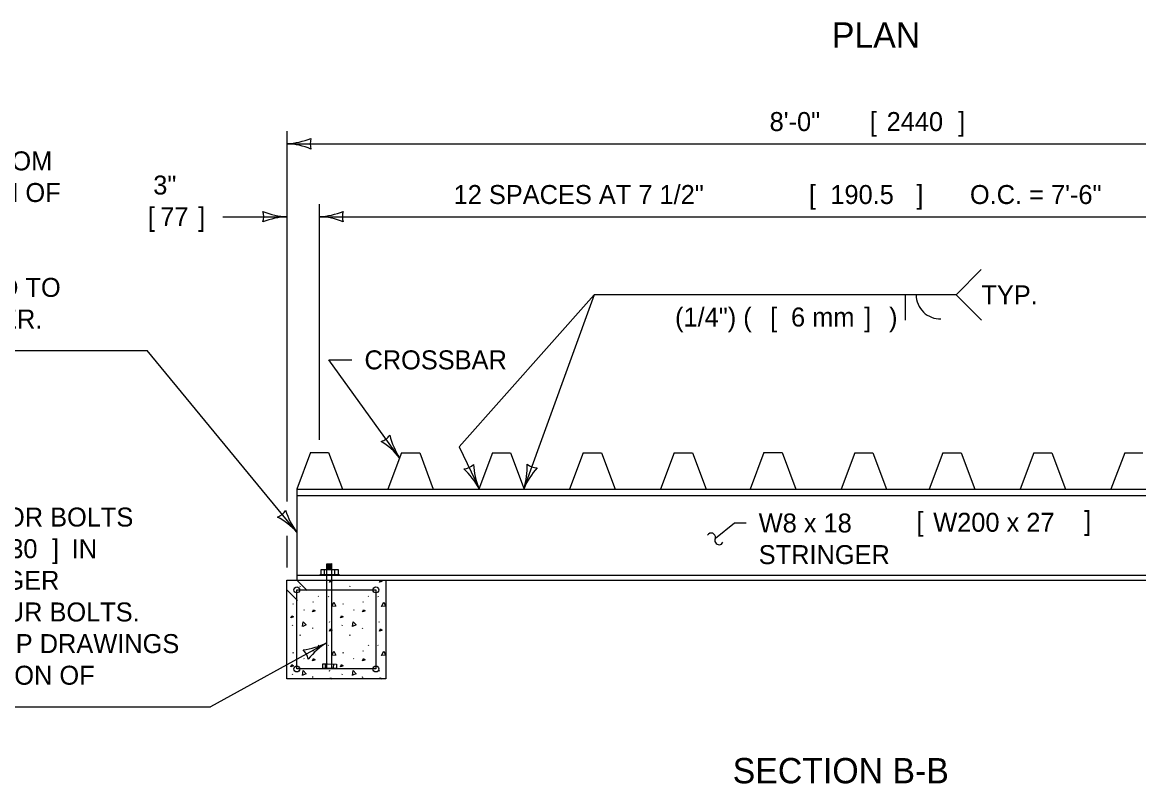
# Model space of a CAD drawing. Extents: x 49991.4 to 50021, y 49987.6 to 50011.4.
# Drawn here: x 50010.101 to 50013.631, y 49993.516 to 49995.923 of the extents above; entities that cross this region are included whole.
import ezdxf

# ---------------------------------------------------------------- set-up
doc = ezdxf.new("R2010")
doc.units = 0
for name, color, linetype in [('Level 1', 7, 'Continuous'), ('Level 2', 7, 'Continuous'), ('Level 3', 7, 'Continuous')]:
    doc.layers.add(name, color=color, linetype=linetype)

msp = doc.modelspace()

# ---------------------------------------------------------------- linework, layer by layer
at = {"layer": 'Level 1'}
for p, q in [((50011.0124, 49994.5626), (50010.9693, 49994.4468)), ((50011.0124, 49994.5626), (50011.0699, 49994.5626)), ((50011.0699, 49994.5626), (50011.1133, 49994.4468)), ((50011.3002, 49994.5619), (50011.2571, 49994.4468)), ((50011.3002, 49994.5619), (50011.3577, 49994.5619)), ((50011.3577, 49994.5619), (50011.4008, 49994.4468)), ((50011.5877, 49994.5619), (50011.5445, 49994.4468)), ((50011.5877, 49994.5619), (50011.6451, 49994.5619)), ((50011.6451, 49994.5619), (50011.6883, 49994.4468)), ((50011.8751, 49994.5619), (50011.8319, 49994.4468)), ((50011.8751, 49994.5619), (50011.9327, 49994.5617)), ((50011.9327, 49994.5617), (50011.9758, 49994.4468)), ((50012.1626, 49994.5617), (50012.1194, 49994.4468)), ((50012.1626, 49994.5617), (50012.2202, 49994.5617)), ((50012.2202, 49994.5617), (50012.2633, 49994.4468)), ((50012.4464, 49994.5623), (50012.4029, 49994.4468)), ((50012.4464, 49994.5623), (50012.504, 49994.5623)), ((50012.504, 49994.5623), (50012.5471, 49994.4468)), ((50012.7334, 49994.5622), (50012.6901, 49994.4468)), ((50012.7334, 49994.5622), (50012.7909, 49994.5622)), ((50012.7909, 49994.5622), (50012.8339, 49994.4468)), ((50013.012, 49994.5622), (50012.9686, 49994.4468)), ((50013.012, 49994.5622), (50013.0695, 49994.5622)), ((50013.0695, 49994.5622), (50013.1127, 49994.4468)), ((50013.2995, 49994.5622), (50013.2561, 49994.4468)), ((50013.2995, 49994.5622), (50013.3571, 49994.5622)), ((50013.3571, 49994.5622), (50013.4002, 49994.4468)), ((50013.5871, 49994.5622), (50013.5436, 49994.4468)), ((50013.5871, 49994.5622), (50013.6444, 49994.5622)), ((50010.9693, 49994.4468), (50014.5501, 49994.4468)), ((50010.9693, 49994.4468), (50010.9693, 49994.1596)), ((50010.9693, 49994.4271), (50014.5501, 49994.4271)), ((50011.064, 49994.2103), (50011.0797, 49994.2114)), ((50011.064, 49993.8801), (50011.064, 49994.2103)), ((50011.0797, 49993.8798), (50011.0797, 49994.2114)), ((50010.9693, 49994.1748), (50014.5501, 49994.1748)), ((50011.1041, 49994.1756), (50011.0416, 49994.1756)), ((50011.0416, 49994.1756), (50011.0416, 49994.1748)), ((50011.046, 49994.1756), (50011.046, 49994.1926)), ((50011.046, 49994.1926), (50011.064, 49994.1926)), ((50011.0572, 49994.1756), (50011.0572, 49994.1926)), ((50011.064, 49994.2075), (50011.0797, 49994.2083)), ((50011.064, 49994.2044), (50011.0797, 49994.2052)), ((50011.064, 49994.2014), (50011.0797, 49994.2022)), ((50011.064, 49994.1983), (50011.0797, 49994.1991)), ((50011.064, 49994.1952), (50011.0797, 49994.196)), ((50011.064, 49994.1926), (50011.0998, 49994.1926)), ((50011.0891, 49994.1756), (50011.0891, 49994.1926)), ((50011.0998, 49994.1926), (50011.0998, 49994.1756)), ((50011.1041, 49994.1756), (50011.1041, 49994.1748)), ((50010.9398, 49994.1596), (50014.5796, 49994.1596)), ((50010.9693, 49994.1596), (50011.0024, 49994.1264)), ((50010.938, 49994.1284), (50010.9712, 49994.0951)), ((50011.0512, 49993.8803), (50011.0514, 49993.8947)), ((50011.0514, 49993.8947), (50011.0658, 49993.8944)), ((50011.0602, 49993.8802), (50011.0604, 49993.8945)), ((50011.0658, 49993.8944), (50011.0946, 49993.894)), ((50011.0855, 49993.8797), (50011.0858, 49993.8941)), ((50011.0946, 49993.894), (50011.0944, 49993.8795)), ((50011.0656, 49993.8801), (50011.0512, 49993.8803)), ((50011.0944, 49993.8795), (50011.0656, 49993.8801))]:
    msp.add_line(p, q, dxfattribs=at)
for points in [[(50010.938, 49994.1596), (50011.2505, 49994.1596), (50011.2505, 49993.8471), (50010.938, 49993.8471)], [(50010.9693, 49994.1284), (50011.2193, 49994.1284), (50011.2193, 49993.8784), (50010.9693, 49993.8784)]]:
    msp.add_lwpolyline(points, close=True, dxfattribs=at)
for centre in [(50010.9693, 49994.1283), (50011.2193, 49994.1283), (50010.9693, 49993.8783), (50011.2193, 49993.8783)]:
    msp.add_circle(centre, 0.00937, dxfattribs=at)
at = {"layer": 'Level 3'}
for p, q in [((50010.938, 49995.579), (50010.938, 49994.4078)), ((50010.938, 49995.539), (50014.5798, 49995.539)), ((50011.04, 49995.3483), (50011.04, 49994.6026)), ((50010.7348, 49995.3083), (50010.938, 49995.3083)), ((50011.04, 49995.3083), (50014.4721, 49995.3083)), ((50013.0539, 49995.0611), (50013.1337, 49995.1408)), ((50011.9098, 49995.061), (50011.4829, 49994.5805)), ((50011.9098, 49995.061), (50011.6876, 49994.4486)), ((50013.0539, 49995.0611), (50011.9098, 49995.061)), ((50012.8935, 49994.9811), (50012.8935, 49995.0611)), ((50013.0539, 49995.0611), (50013.1339, 49994.9811)), ((50009.6685, 49994.8847), (50010.4962, 49994.8847)), ((50010.9693, 49994.3106), (50010.4962, 49994.8847)), ((50011.0701, 49994.8556), (50011.1431, 49994.8556)), ((50011.2943, 49994.546), (50011.0701, 49994.8556)), ((50011.4829, 49994.5805), (50011.5454, 49994.4493)), ((50012.2928, 49994.2918), (50012.3533, 49994.3399)), ((50012.3533, 49994.3399), (50012.3898, 49994.3399)), ((50010.938, 49994.2993), (50010.938, 49994.1996)), ((50010.9795, 49994.1389), (50010.9806, 49994.1413)), ((50011.1371, 49994.1389), (50011.1382, 49994.1413)), ((50011.0368, 49994.1089), (50011.0379, 49994.1073)), ((50011.0679, 49994.1083), (50011.0689, 49994.1067)), ((50011.1944, 49994.1089), (50011.1955, 49994.1073)), ((50011.2255, 49994.1083), (50011.2266, 49994.1067)), ((50010.958, 49994.083), (50010.959, 49994.0854)), ((50011.0211, 49994.0892), (50011.0222, 49994.0916)), ((50011.1156, 49994.083), (50011.1166, 49994.0854)), ((50011.1787, 49994.0892), (50011.1798, 49994.0916)), ((50010.9913, 49994.066), (50010.9923, 49994.0644)), ((50011.0192, 49994.0591), (50011.0224, 49994.0657)), ((50011.0277, 49994.0617), (50011.0192, 49994.0591)), ((50011.0224, 49994.0657), (50011.0277, 49994.0617)), ((50011.1489, 49994.066), (50011.1499, 49994.0644)), ((50011.1768, 49994.0591), (50011.18, 49994.0657)), ((50011.1854, 49994.0617), (50011.1768, 49994.0591)), ((50011.18, 49994.0657), (50011.1854, 49994.0617)), ((50010.9553, 49994.0154), (50010.9564, 49994.0178)), ((50011.0186, 49994.0087), (50011.0189, 49994.0063)), ((50011.0724, 49994.0263), (50011.0735, 49994.0287)), ((50011.1129, 49994.0154), (50011.114, 49994.0178)), ((50011.1762, 49994.0087), (50011.1765, 49994.0063)), ((50011.23, 49994.0263), (50011.2311, 49994.0287)), ((50010.9795, 49993.9845), (50010.9806, 49993.9869)), ((50011.1371, 49993.9845), (50011.1382, 49993.9869)), ((50011.064, 49993.9611), (50010.6967, 49993.7586)), ((50010.958, 49993.9286), (50010.959, 49993.931)), ((50011.0211, 49993.9347), (50011.0222, 49993.9371)), ((50011.0368, 49993.9545), (50011.0379, 49993.9529)), ((50011.0679, 49993.9539), (50011.0689, 49993.9523)), ((50011.1156, 49993.9286), (50011.1166, 49993.931)), ((50011.1787, 49993.9347), (50011.1798, 49993.9371)), ((50011.1944, 49993.9545), (50011.1955, 49993.9529)), ((50011.2255, 49993.9539), (50011.2266, 49993.9523)), ((50010.9913, 49993.9115), (50010.9923, 49993.9099)), ((50011.0192, 49993.9046), (50011.0224, 49993.9113)), ((50011.0277, 49993.9073), (50011.0192, 49993.9046)), ((50011.0224, 49993.9113), (50011.0277, 49993.9073)), ((50011.1489, 49993.9115), (50011.1499, 49993.9099)), ((50011.1768, 49993.9046), (50011.18, 49993.9113)), ((50011.1854, 49993.9073), (50011.1768, 49993.9046)), ((50011.18, 49993.9113), (50011.1854, 49993.9073)), ((50010.9553, 49993.8609), (50010.9564, 49993.8633)), ((50011.0724, 49993.8718), (50011.0735, 49993.8742)), ((50011.1129, 49993.8609), (50011.114, 49993.8633)), ((50011.23, 49993.8718), (50011.2311, 49993.8742)), ((50011.0186, 49993.8542), (50011.0189, 49993.8518)), ((50011.1762, 49993.8542), (50011.1765, 49993.8518)), ((50009.9843, 49993.7586), (50010.6967, 49993.7586))]:
    msp.add_line(p, q, dxfattribs=at)
for points in [[(50011.0729, 49994.1528), (50011.0761, 49994.1594), (50011.0815, 49994.1554), (50011.0729, 49994.1528)], [(50011.2306, 49994.1528), (50011.2337, 49994.1594), (50011.2391, 49994.1554), (50011.2306, 49994.1528)], [(50011.0796, 49994.0758), (50011.0868, 49994.0894), (50011.0924, 49994.0769), (50011.0799, 49994.0758)], [(50011.2372, 49994.0758), (50011.2444, 49994.0894), (50011.25, 49994.0769), (50011.2375, 49994.0758)], [(50010.95, 49994.04), (50010.9532, 49994.0467), (50010.9585, 49994.0427), (50010.95, 49994.04)], [(50011.1076, 49994.04), (50011.1108, 49994.0467), (50011.1161, 49994.0427), (50011.1076, 49994.04)], [(50010.9877, 49994.0126), (50010.9898, 49994.0278), (50010.9993, 49994.018), (50010.9879, 49994.0127)], [(50011.0729, 49993.9983), (50011.0761, 49994.005), (50011.0815, 49994.001), (50011.0729, 49993.9983)], [(50011.1453, 49994.0126), (50011.1474, 49994.0278), (50011.157, 49994.018), (50011.1456, 49994.0127)], [(50011.2306, 49993.9983), (50011.2337, 49994.005), (50011.2391, 49994.001), (50011.2306, 49993.9983)], [(50011.0796, 49993.9214), (50011.0868, 49993.935), (50011.0924, 49993.9225), (50011.0799, 49993.9214)], [(50011.2372, 49993.9214), (50011.2444, 49993.935), (50011.25, 49993.9225), (50011.2375, 49993.9214)], [(50010.95, 49993.8856), (50010.9532, 49993.8922), (50010.9585, 49993.8882), (50010.95, 49993.8856)], [(50011.1076, 49993.8856), (50011.1108, 49993.8922), (50011.1161, 49993.8882), (50011.1076, 49993.8856)], [(50010.9877, 49993.8582), (50010.9898, 49993.8734), (50010.9993, 49993.8635), (50010.9879, 49993.8583)], [(50011.1453, 49993.8582), (50011.1474, 49993.8734), (50011.157, 49993.8635), (50011.1456, 49993.8583)], [(50011.0745, 49993.8471), (50011.0761, 49993.8505), (50011.0807, 49993.8471)], [(50011.2321, 49993.8471), (50011.2337, 49993.8505), (50011.2383, 49993.8471)]]:
    msp.add_lwpolyline(points, dxfattribs=at)
for centre, radius, start, end in [((50010.9265, 49995.7717), 0.233, 272.8273, 292.0772), ((50011.0662, 49995.539), 0.0548, 162.1388, 197.8612), ((50010.9288, 49995.3169), 0.2223, 67.456, 87.6395), ((50010.9472, 49995.5304), 0.2223, 247.456, 267.6395), ((50010.8098, 49995.3083), 0.0548, 342.1388, 17.8612), ((50010.9495, 49995.0756), 0.233, 92.8273, 112.0772), ((50011.0285, 49995.541), 0.233, 272.8273, 292.0772), ((50011.0308, 49995.0862), 0.2223, 67.456, 87.6395), ((50011.1682, 49995.3083), 0.0548, 162.1388, 197.8612), ((50013.0048, 49995.0624), 0.0776, 180.9348, 270.9635), ((50011.2191, 49994.6499), 0.0548, 288.0459, 323.7683), ((50011.4796, 49994.6689), 0.2223, 193.3631, 213.5466), ((50011.1125, 49994.4003), 0.233, 38.7344, 57.9842), ((50011.4903, 49994.565), 0.0548, 277.6284, 313.3508), ((50011.3403, 49994.3388), 0.233, 28.3169, 47.5668), ((50011.7499, 49994.5366), 0.2223, 182.9456, 203.1291), ((50011.465, 49994.5171), 0.233, 342.8887, 2.1385), ((50011.8933, 49994.3642), 0.2223, 137.5174, 157.7009), ((50011.7314, 49994.5691), 0.0548, 232.2002, 267.9225), ((50010.8878, 49994.4096), 0.0548, 291.6279, 327.3503), ((50010.797, 49994.1538), 0.233, 42.3164, 61.5662), ((50011.1466, 49994.4448), 0.2223, 196.9451, 217.1286), ((50012.2795, 49994.2945), 0.0136, 348.5802, 150.9388), ((50012.3044, 49994.2848), 0.0136, 148.6595, 334.3301), ((50010.9648, 49994.1601), 0.2223, 276.3236, 296.5071), ((50010.9517, 49993.8992), 0.0548, 11.0064, 46.7287), ((50011.1864, 49993.7629), 0.233, 121.6949, 140.9447)]:
    msp.add_arc(centre, radius, start, end, dxfattribs=at)

# ---------------------------------------------------------------- texts
at = {"layer": 'Level 2'}
for s, height, p in [('PLAN', 0.08, (50012.6611, 49995.8427)), ('8\'-0" ', 0.06, (50012.4643, 49995.579)), ('[', 0.06, (50012.781, 49995.579)), ('2440', 0.06, (50012.8343, 49995.579)), (']', 0.06, (50013.0607, 49995.579)), ('NOTE:  EXTEND END PLATE FROM', 0.06, (50008.8541, 49995.4547)), ('TOP OF STRINGER TO BOTTOM OF', 0.06, (50008.8541, 49995.3547)), ('3"', 0.06, (50010.5153, 49995.3783)), ('12 SPACES AT 7 1/2" ', 0.06, (50011.465, 49995.3483)), ('[', 0.06, (50012.5884, 49995.3483)), (']', 0.06, (50012.9281, 49995.3483)), ('190.5', 0.06, (50012.6563, 49995.3483)), (' O.C. = 7\'-6" ', 0.06, (50013.0754, 49995.3483)), ('[', 0.06, (50010.4978, 49995.2783)), (']', 0.06, (50010.6575, 49995.2783)), ('77', 0.06, (50010.5375, 49995.2783)), ('SYMMETRICALLY DISTRIBUTED TO', 0.06, (50008.8541, 49995.0547)), ('TYP.', 0.06, (50013.1339, 49995.0311)), ('(1/4") (', 0.06, (50012.1652, 49994.961)), ('[', 0.06, (50012.4658, 49994.961)), ('6 mm', 0.06, (50012.532, 49994.961)), (']', 0.06, (50012.7634, 49994.961)), (')', 0.06, (50012.842, 49994.961)), ('FLANGE AND WEB OF STRINGER.', 0.06, (50008.8541, 49994.9547)), ('CROSSBAR', 0.06, (50011.1831, 49994.8256)), ('3/4" DIA. [M19] ANCHOR BOLTS', 0.06, (50009.2556, 49994.3286)), ('W8 x 18 ', 0.06, (50012.4298, 49994.3099)), ('[', 0.06, (50012.9283, 49994.315)), ('W200 x 27', 0.06, (50012.9817, 49994.3121)), (']', 0.06, (50013.4589, 49994.3173)), ('230', 0.06, (50010.0153, 49994.2286)), (']', 0.06, (50010.1953, 49994.2286)), (' IN', 0.06, (50010.235, 49994.2286)), ('STRINGER', 0.06, (50012.4298, 49994.2099)), ('CONC.; EACH STRINGER', 0.06, (50009.2556, 49994.1286)), ('ATTACHED WITH FOUR BOLTS.  ', 0.06, (50009.2556, 49994.0286)), ('SEE APPROVED SHOP DRAWINGS', 0.06, (50009.2556, 49993.9286)), ('FOR ACTUAL LOCATION OF', 0.06, (50009.2556, 49993.8286)), ('SECTION B-B', 0.08, (50012.3475, 49993.5169))]:
    msp.add_text(s, height=height, dxfattribs=at).set_placement(p)

doc.saveas('drawing.dxf')
